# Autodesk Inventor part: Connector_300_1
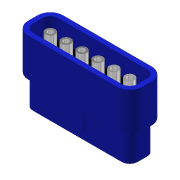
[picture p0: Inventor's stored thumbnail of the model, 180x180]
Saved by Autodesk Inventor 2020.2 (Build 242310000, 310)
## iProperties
Created: 2014-09
Part Number: Connector_300_1
Material: Ogólny
Document SubType Name: Modeling
Designer: F.Stasiak
Density: 1 g/cm^3
Appearance: Domyślna
Categories: <MemberInstance><Categories><Category DisplayName="" Mnemonic="CABLEANDHARNESS" InternalName="e4a7e005-5e42-4d16-b293-125e7f0d0512"><Category DisplayName="" Mne
Catalog Web Link: www.expertbooks.pl
Manager: www.cadconsulting.pl
Company: Fabian Stasiak CAD Consulting
Author: F.Stasiak
Subject: Zbiór ćwiczeń. Autodesk Inventor 2020. Kurs Professional
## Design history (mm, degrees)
sketch "Szkic1"
  geometry: L1 (0, 0)-(30, 0); L2 (0, 2.5)-(30, 2.5); L3 (30, 2.5)-(30, -2.5); L4 (30, -2.5)-(0, -2.5); L5 (0, -2.5)-(0, 2.5); 7 further points
  constraints: 10 end point, 2 horizontal, 2 parallel, 1 coincident, 1 midpoint, 1 perpendicular
  dimensions: "d0" = 5 distance of point (7.5, 0) point (2.5, 0); "d1" = 5 distance of point (12.5, 0) point (7.5, 0) (= d0); "d2" = 5 distance of point (17.5, 0) point (12.5, 0) (= d0); "d3" = 5 distance of point (22.5, 0) point (17.5, 0) (= d0); "d4" = 5 distance of point (22.5, 0) point (27.5, 0) (= d0); "d16" = 2.5 distance of point (2.5, 0) L1.start; "d17" = 2.5 distance of point (27.5, 0) L1.end (= d16); "d18" = 5 distance of L4.end L2.start; "d19" = 30 distance of L3.end L4.end (= 0.5 x LPINÓW)
node "Oś konstrukcyjna1"
node "Oś konstrukcyjna2"
node "Oś konstrukcyjna3"
node "Oś konstrukcyjna4"
node "Oś konstrukcyjna5"
node "Oś konstrukcyjna6"
extrude "Wyciągnięcie proste3" new body sketch "Szkic1" distance "d20" = 3; taper "d21" = 0 deg
sketch "Szkic3"
  geometry: C1 r 1 at (2.5, 0); 2 further points
  constraints: 1 centre point, 1 coincident
  dimensions: "d22" = 2 diameter of C1
extrude "Wyciągnięcie proste4" join sketch "Szkic3" distance "d23" = 5; taper "d24" = 0 deg; dims "d29" = 15, "d30" = 0
sketch "Szkic4"
  geometry: C1 r 1.5 at (0, 0)
  constraints: 1 centre point
  dimensions: "d31" = 3 diameter of C1
extrude "Wyciągnięcie proste5" join sketch "Szkic4" stored distance "d32" = 0; taper "d33" = 0 deg
sketch "Szkic5"
  geometry: C1 r 0.9 at (0, 0)
  constraints: 1 centre point
  dimensions: "d34" = 1.8 diameter of C1
extrude "Wyciągnięcie proste6" cut sketch "Szkic5" distance "d35" = 7; taper "d36" = 0 deg
fillet "Zaokrąglenie3" dims "d45" = 1
pattern_linear "Szyk prostokątny2" dims "d27" = 5
node "Płaszczyzna konstrukcyjna1"
sketch "Szkic6"
  geometry: L1 (0, -2.5)-(30, -2.5) reference; L2 (30, -2.5)-(30, 2.5) reference; L3 (30, 2.5)-(0, 2.5) reference; L4 (0, 2.5)-(0, -2.5) reference; L5 (31.5, -4)-(-1.5, -4); L6 (-1.5, -4)-(-1.5, 4); L7 (-1.5, 4)-(31.5, 4); L8 (31.5, 4)-(31.5, -4)
  constraints: 8 end point, 3 other
  dimensions: "d37" = 1.5 distance between parallel lines of L5 L1
extrude "Wyciągnięcie proste7" join sketch "Szkic6" distance "d38" = 15.25; taper "d39" = 0 deg
fillet "Zaokrąglenie1" dims "d40" = 1
fillet "Zaokrąglenie2" dims "d41" = 2.5
chamfer "Faza1" distance "d42" = 1.05; stored, may be unused: second distance "d43" = 11, angle "d44" = 45 deg
sketch "Szkic7"
  geometry: L1 (-1.5, -1.5)-(-1.5, 1.5) reference; L2 (29, -4)-(1, -4) reference; L3 (31.5, 1.5)-(31.5, -1.5) reference; L4 (1, 4)-(29, 4) reference; L5 (-3, -1.5)-(-3, 1.5); L6 (1, 5.5)-(29, 5.5); L7 (33, 1.5)-(33, -1.5); L8 (29, -5.5)-(1, -5.5); C1 r 1.5 at (12.5, 0) reference; C2 r 1.5 at (7.5, 0) reference; C3 r 1.5 at (2.5, 0) reference; A1 r 2.5 centre (1, 1.5) between (1, 4) and (-1.5, 1.5) reference; A2 r 2.5 centre (1, -1.5) between (-1.5, -1.5) and (1, -4) reference; A3 r 2.5 centre (29, -1.5) between (29, -4) and (31.5, -1.5) reference; A4 r 2.5 centre (29, 1.5) between (31.5, 1.5) and (29, 4) reference; A5 r 4 centre (1, -1.5) between (-3, -1.5) and (1, -5.5); A6 r 4 centre (1, 1.5) between (1, 5.5) and (-3, 1.5); A7 r 4 centre (29, 1.5) between (33, 1.5) and (29, 5.5); A8 r 4 centre (29, -1.5) between (29, -5.5) and (33, -1.5)
  constraints: 8 end point, 8 point on circle, 4 centre point, 7 other
  dimensions: "d46" = 1.5 distance between parallel lines of L2 L8
extrude "Wyciągnięcie proste8" join sketch "Szkic7" stored distance "d47" = 12; taper "d48" = 0 deg
sketch "Szkic8"
  geometry: L1 (-1, 4)-(-29, 4) reference; L2 (1.5, -1.5)-(1.5, 1.5) reference; L3 (-29, -4)-(-1, -4) reference; L4 (-31.5, 1.5)-(-31.5, -1.5) reference; L5 (3, -1.5)-(3, 1.5) reference; L6 (-1, 5.5)-(-29, 5.5) reference; L7 (-33, 1.5)-(-33, -1.5) reference; L8 (-29, -5.5)-(-1, -5.5) reference; L9 (-12, -5.5)-(-18, -5.5); L10 (-18, -5.5)-(-18, -4); L11 (-18, -4)-(-12, -4); L12 (-12, -4)-(-12, -5.5); A1 r 2.5 centre (-1, 1.5) between (1.5, 1.5) and (-1, 4) reference; A2 r 2.5 centre (-1, -1.5) between (-1, -4) and (1.5, -1.5) reference; A3 r 2.5 centre (-29, -1.5) between (-31.5, -1.5) and (-29, -4) reference; A4 r 2.5 centre (-29, 1.5) between (-29, 4) and (-31.5, 1.5) reference; A5 r 4 centre (-1, -1.5) between (-1, -5.5) and (3, -1.5) reference; A6 r 4 centre (-1, 1.5) between (3, 1.5) and (-1, 5.5) reference; A7 r 4 centre (-29, 1.5) between (-29, 5.5) and (-33, 1.5) reference; A8 r 4 centre (-29, -1.5) between (-33, -1.5) and (-29, -5.5) reference; 2 further points
  constraints: 8 end point, 4 midpoint, 2 parallel, 1 horizontal, 1 perpendicular
  dimensions: "d49" = 6 distance of L9.start L9.end
extrude "Wyciągnięcie proste9" join sketch "Szkic8" distance "d50" = 6.5; taper "d51" = 0 deg
node "Punkt konstrukcyjny2"
node "Punkt konstrukcyjny3"
node "Punkt konstrukcyjny4"
node "Punkt konstrukcyjny5"
node "Punkt konstrukcyjny6"
node "Punkt konstrukcyjny7"
node "Bryła2"
node "Pętla rzutowana1"
node "Pętla rzutowana2"
other parameters: "d28" = 8
